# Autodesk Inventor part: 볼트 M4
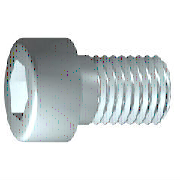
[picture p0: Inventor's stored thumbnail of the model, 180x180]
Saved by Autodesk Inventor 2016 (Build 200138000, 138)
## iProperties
IsCustomPart: 1
Created: 2012-02
Part Number: 볼트 M4
Material: 스테인리스강
Description: 6각 소켓 머리 캡 나사
Document SubType Name: Modeling
Standard: ISO 4762
Designer: mduedu
Standard Revision: Fourth edition 2004-03-01
Standards Organization: ISO
Language: ko-KR
Size Designation: M4 x 10
Categories: <MemberInstance><Categories><Category DisplayName="조임쇠" InternalName="e4da775c-781d-43d5-af7c-5136215cf5a6" Mnemonic="FSTN"><Category DisplayName="볼트" InternalN
Density: 7.75 g/cm^3
Appearance: 반광택
Author: mduedu
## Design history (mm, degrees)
sketch "스케치1"
  geometry: L1 (-1, 0)-(10, 0); L2 (10, 0)-(10, 2); L3 (10, 2)-(1.75, 2); L4 (1.75, 2)-(1.32, 2); L5 (1.32, 2)-(0, 2); L6 (0, 2)-(0, 3.5); L7 (0, 3.5)-(-4, 3.5); L8 (-4, 3.5)-(-4, 1.732); L9 (-4, 1.732)-(-2, 1.732); L10 (-2, 1.732)-(-1, 0); L11 (-6.8, 0)-(12.8, 0) reference; L12 (0, -0.7)-(0, 4.2) reference; L13 (1.75, 2)-(0, 2)
  constraints: 22 end point, 6 parallel, 2 collinear, 2 perpendicular, 1 horizontal, 1 point on line
  dimensions: "d1" = 8.25 distance from line of L3.end L2 (= GEL); "d2" = 0.42952 distance of L4.end L3.end (computed from GAL); "d3" = 4 distance between parallel lines of L8 L6 (= KOH); "d4" = 2 distance of L8.end L9.end (= INTI); "d5" = 60 deg angle of L10 L1; "d6" = 4 diameter of L3 L1 (= GD); "d7" = 4 diameter of L5 L1 (= BDM); "d8" = 3.4641 diameter of L9 L1 (= 1.1547 x SW); "d9" = 7 diameter of L7 L1 (= KOD); "d26" = 10 distance between parallel lines of L12 L2 (= NLG)
revolve "본체" sketch "스케치1" stored, may be unused: angle "d10" = 90 deg
sketch "스케치2"
  geometry: L1 (0, -4.9)-(0, 4.9) reference; L2 (-4.9, 0)-(4.9, 0) reference; L3 (1.732, 0)-(0.866, -1.5); L4 (0.866, -1.5)-(-0.866, -1.5); L5 (-0.866, -1.5)-(-1.732, 0); L6 (-1.732, 0)-(-0.866, 1.5); L7 (-0.866, 1.5)-(0.866, 1.5); L8 (0.866, 1.5)-(1.732, 0); 2 further points
  constraints: 12 end point, 1 coincident, 1 horizontal alignment, 1 point on line, 12 other
extrude "슬롯" join sketch "스케치2" stored distance "d11" = 10; taper "d12" = 0 deg
workplane "Work Plane1"
body "Solid1"
fillet "모깎기1" dims "d17" = 0.4 (= RR)
feature "스레드" dims "d13" = 8.25 (= GEL), "d14" = 0
chamfer "모따기1" distance "d15" = 0.42941 (= -0.5 x SPD + 0.5 x GD); stored, may be unused: second distance "d16" = 0.42941 (= GUL), angle "d27" = 45 deg
other parameters: "GD" = 4 [user parameter; used in 2 equation terms], "NLG" = 10 [user parameter; used in 1 equation term], "GEL" = 8.25 [user parameter; used in 2 equation terms], "KOD" = 7 [user parameter; used in 1 equation term], "KOH" = 4 [user parameter; used in 1 equation term], "INTI" = 2 [user parameter; used in 1 equation term], "GAL" = 0.42941 (= 0.61345 x PTC) [user parameter; used in 1 equation term], "GUL" = 0.42941 (= 0.61345 x PTC) [user parameter; used in 1 equation term], "BDM" = 4 (= NND) [user parameter; used in 1 equation term], "SW" = 3 [user parameter; used in 2 equation terms], "RR" = 0.4 [user parameter; used in 1 equation term], "SPD" = 3.14117 (= NND - 1.2269 x PTC) [user parameter; used in 1 equation term], "d19" = 0, "d28" = 0, "d29" = 0, "R" = 0.1 [user parameter], "TOA" = 30 deg [user parameter], "GD1" = 3.14117 (= THREADDIA - 1.2269 x PTC) [user parameter], "THREADDIA" = 4 [user parameter; used in 1 equation term], "FAWI" = 45 deg [user parameter], "TPU" = 14.28571 (computed from PTC) [user parameter], "PTC" = 0.7 [user parameter; used in 5 equation terms], "NND" = 4 [user parameter; used in 2 equation terms], "E0" = 3.465 (= 1.155 x SW) [user parameter]
